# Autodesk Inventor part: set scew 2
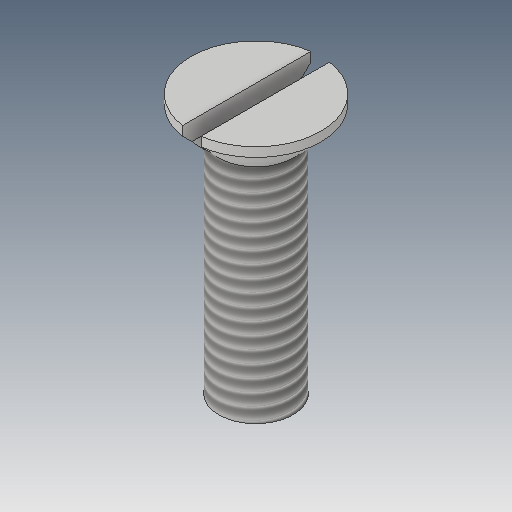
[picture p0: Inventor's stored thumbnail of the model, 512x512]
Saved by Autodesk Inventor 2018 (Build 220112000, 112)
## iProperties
Created: 2016-06
Part Number: set scew 2
Material: Generic
Document SubType Name: Modeling
Designer: CADCIM
Density: 1 g/cm^3
Appearance: Default
Mass: 0.690766 g
Surface Area: 5.88069 cm^2
Volume: 0.690766 cm^3
Author: CADCIM
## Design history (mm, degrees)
sketch "Sketch1"
  geometry: C1 r 3 at (0, 0); 1 further point
  constraints: 1 centre point, 1 coincident
  dimensions: "d0" = 6 diameter of C1
extrude "Extrusion1" new body sketch "Sketch1" distance "d1" = 18; taper "d2" = 0 deg
sketch "Sketch2"
  geometry: L1 (18, -3)-(18, 3) reference; L2 (18, 0)-(18, -3); L3 (18, -3)-(21, -6); L4 (21, -6)-(21, 0); L5 (21, 0)-(18, 0); 1 further point
  constraints: 8 end point, 2 vertical, 1 midpoint, 1 perpendicular
  dimensions: "d4" = 3 distance of L2.start L2.end; "d5" = 6 distance of L4.end L3.end; "d6" = 3 distance from line of L1.start L4
revolve "Revolution1" sketch "Sketch2" stored, may be unused: angle "d7" = 90 deg
sketch "Sketch3"
  geometry: C1 r 5.25 at (0, 0); 1 further point
  constraints: 1 centre point, 1 coincident
  dimensions: "d8" = 10.5 diameter of C1
extrude "Extrusion2" sketch "Sketch3" distance "d9" = 26.75; taper "d10" = 0 deg
sketch "Sketch4"
  geometry: L1 (-0.75, 8.347)-(0.75, 8.347); L2 (0.75, 8.347)-(0.75, -8.125); L3 (0.75, -8.125)-(-0.75, -8.125); L4 (-0.75, -8.125)-(-0.75, 8.347); L5 (0, 0)-(0, 6.165)
  constraints: 10 end point, 3 parallel, 1 horizontal, 1 perpendicular, 1 other
  dimensions: "d11" = 1.5 distance of L1.start L1.end
extrude "Extrusion3" cut sketch "Sketch4" distance "d12" = 1.5; taper "d13" = 0 deg
sketch "Sketch5"
  geometry: L1 (0, 0)-(0, 3); L2 (0, 3)-(-1.732, 0); L3 (-1.732, 0)-(0, 0); L4 (0, 3)-(0, -3) reference; 1 further point
  constraints: 6 end point, 2 midpoint, 1 perpendicular, 1 point on line, 1 vertical
  dimensions: "d21" = 60 deg angle of L2 L3; "d22" = 3 distance of L1.start L1.end
thread "Thread2" dims "d19" = 10, "d20" = 0
revolve "Revolution3" stored, may be unused: angle "d23" = 90 deg
body "Solid1"
